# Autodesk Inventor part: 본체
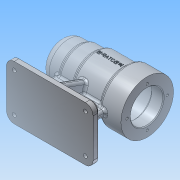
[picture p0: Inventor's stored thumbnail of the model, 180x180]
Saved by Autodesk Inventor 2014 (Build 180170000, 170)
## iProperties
Created: 2016-06
Part Number: 본체
Material: 알루미늄 6061
Document SubType Name: Modeling
Designer: net
Density: 2.71 g/cm^3
Appearance: 알루미늄 - 평지
Author: net
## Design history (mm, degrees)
sketch "스케치2"
  geometry: L1 (46, 35)-(-46, 35); L2 (-56, 25)-(-56, -25); L3 (-46, -35)-(46, -35); L4 (56, -25)-(56, 25); A1 r 10 centre (46, -25) between (46, -35) and (56, -25); A2 r 10 centre (46, 25) between (56, 25) and (46, 35); A3 r 10 centre (-46, 25) between (-46, 35) and (-56, 25); A4 r 10 centre (-46, -25) between (-56, -25) and (-46, -35); 1 further point
  constraints: 8 end point, 8 point on circle, 8 tangent, 4 centre point, 3 equal radius, 2 parallel, 1 horizontal, 1 perpendicular
  dimensions: "d5" = 10 radius of A1
extrude "돌출1" new body sketch "스케치2" distance "d6" = 10; taper "d7" = 0 deg
sketch "스케치3"
  geometry: A1 r 10 centre (-46, 25) between (-46, 35) and (-56, 25) reference; A2 r 10 centre (-46, -25) between (-56, -25) and (-46, -35) reference; A3 r 10 centre (46, -25) between (46, -35) and (56, -25) reference; A4 r 10 centre (46, 25) between (56, 25) and (46, 35) reference; 5 further points
  constraints: 4 coincident
hole "구멍1" sketch "스케치3" at (46, -25), (46, 25), (-46, 25), (-46, -25) diameter "d8" = 5; stored, may be unused: countersink angle "d12" = 90 deg, drill point angle "d14" = 118 deg; dims "d9" = 6, "d10" = 9, "d11" = 4, "d13" = 8
sketch "스케치4"
  geometry: L1 (-56, -25)-(-56, 25) reference; L2 (-46, 35)-(46, 35) reference; L3 (56, 25)-(56, -25) reference; L4 (46, -35)-(-46, -35) reference; L5 (36, 4)-(36, -4); L6 (-36, -4)-(-36, 4); L7 (-4, 28)-(4, 28); L8 (4, -28)-(-4, -28); L9 (4, -28)-(4, -4); L10 (4, 4)-(4, 28); L11 (-4, -28)-(-4, -4); L12 (-4, 4)-(-4, 28); L13 (-36, -4)-(-4, -4); L14 (4, -4)-(36, -4); L15 (-36, 4)-(-4, 4); L16 (4, 4)-(36, 4); C1 r 2.5 at (46, -25) reference; C2 r 2.5 at (-46, 25) reference; C3 r 2.5 at (-46, -25) reference; C4 r 2.5 at (46, 25) reference; A1 r 10 centre (-46, -25) between (-56, -25) and (-46, -35) reference; A2 r 10 centre (-46, 25) between (-46, 35) and (-56, 25) reference; A3 r 10 centre (46, 25) between (56, 25) and (46, 35) reference; A4 r 10 centre (46, -25) between (46, -35) and (56, -25) reference; 1 further point
  constraints: 24 end point
  dimensions: "d15" = 20 distance between parallel lines of L3 L5; "d16" = 20 distance between parallel lines of L6 L1; "d17" = 7 distance between parallel lines of L2 L7; "d18" = 7 distance between parallel lines of L4 L8
extrude "돌출2" join sketch "스케치4" distance "d23" = 70; taper "d24" = 0 deg
sketch "스케치5"
  geometry: L1 (0, 0)-(0, 10) reference; L2 (0, 10)-(50, 10) reference; L3 (50, 0)-(50, 10) reference; L4 (50, 0)-(0, 0) reference; L5 (21, 70)-(29, 70) reference; C1 r 25 at (25, 70); 1 further point
  constraints: 1 centre point, 1 midpoint
  dimensions: "d27" = 50 diameter of C1
extrude "돌출3" join sketch "스케치5" distance "d28" = 112; taper "d29" = 0 deg
node "작업 평면1"
sketch "스케치6"
  geometry: C1 r 27 at (0, 0); 1 further point
  constraints: 1 centre point
  dimensions: "d31" = 54 diameter of C1
extrude "돌출4" join sketch "스케치6" distance "d32" = 20; taper "d33" = 0 deg
sketch "스케치7"
  geometry: C1 r 30 at (0, 0); A1 r 25 centre (0, 0) between (4, -24.678) and (-4, -24.678) reference; 1 further point
  constraints: 1 centre point, 1 coincident
  dimensions: "d34" = 60 diameter of C1
extrude "돌출5" join sketch "스케치7" distance "d35" = 39; taper "d36" = 0 deg
sketch "스케치8"
  geometry: C1 r 34 at (0, 0); A1 r 30 centre (0, 0) between (4, -29.732) and (-4, -29.732) reference; 1 further point
  constraints: 1 centre point, 1 coincident
  dimensions: "d37" = 68 diameter of C1
extrude "돌출6" join sketch "스케치8" distance "d38" = 28; taper "d39" = 0 deg
feature "면 기울기1" dims angle "d40" = 20 deg
sketch "스케치9"
  geometry: C1 r 34 at (0, 0) reference; C2 r 21 at (0, 0); 1 further point
  constraints: 1 centre point, 1 coincident
  dimensions: "d41" = 42 diameter of C2
extrude "돌출7" cut sketch "스케치9" distance "d42" = 15; taper "d43" = 0 deg
sketch "스케치10"
  geometry: C1 r 21 at (0, 0) reference; C2 r 24 at (0, 0); 1 further point
  constraints: 1 centre point, 1 coincident
  dimensions: "d44" = 48 diameter of C2
extrude "돌출8" cut sketch "스케치10" distance "d45" = 54; taper "d46" = 0 deg
sketch "스케치11"
  geometry: C1 r 24 at (0, 0) reference; C2 r 21 at (0, 0); 1 further point
  constraints: 1 centre point, 1 coincident
  dimensions: "d47" = 42 diameter of C2
extrude "돌출9" cut sketch "스케치11" distance "d48" = 12; taper "d49" = 0 deg
sketch "스케치12"
  geometry: C1 r 21 at (0, 0) reference; C2 r 17.5 at (0, 0); 1 further point
  constraints: 1 centre point, 1 coincident
  dimensions: "d50" = 35 diameter of C2
extrude "돌출10" cut sketch "스케치12" distance "d51" = 18; taper "d52" = 0 deg
chamfer "모따기1" distance "d53" = 4; stored, may be unused: second distance "d54" = 2, angle "d55" = 45 deg
chamfer "모따기2" distance "d56" = 1; stored, may be unused: second distance "d57" = 2, angle "d58" = 45 deg
fillet "모깎기1" dims "d59" = 10
sketch "스케치13"
  geometry: C1 r 17.5 at (0, 0) reference; C2 r 10.5 at (0, 0); 1 further point
  constraints: 1 centre point, 1 coincident
  dimensions: "d60" = 21 diameter of C2
extrude "돌출11" cut sketch "스케치13" distance "d61" = 3; taper "d62" = 0 deg
fillet "모깎기2" dims "d63" = 3
fillet "모깎기3" dims "d64" = 3
fillet "모깎기4" dims "d65" = 3
fillet "모깎기5" dims "d66" = 3
fillet "모깎기6" dims "d67" = 3
fillet "모깎기7" dims "d68" = 3
fillet "모깎기8" dims "d69" = 3
node "작업 평면2"
sketch "스케치14"
  geometry: L1 (56, 36)-(56, 104) reference; L2 (56, 36)-(56, 70); 2 further points
  constraints: 2 end point, 1 midpoint, 1 other
  dimensions: "d71" = 48 distance from line of point (8, 70) L1; "d72" = 0 vertical distance of point (8, 70) L2.end
feature "엠보싱1" sketch "스케치14" dims "d73" = 0.5, "d74" = 0
sketch "스케치15"
  geometry: C1 r 34 at (0, 0) reference; C2 r 22 at (0, 0) reference; 6 further points
  constraints: 1 coincident, 6 other
  dimensions: "d75" = 26 distance of point (26, 0) C1.centre; "d78" = 360 deg dimension on point (0, 0) point (26, 0) (derived)
hole "구멍2" sketch "스케치15" at (0, 26), (26, 0), (0, -26), (-26, 0) diameter "d80" = 3.242; stored, may be unused: countersink angle "d84" = 90 deg, drill point angle "d86" = 118 deg; dims "d81" = 8, "d82" = 4, "d83" = 2, "d85" = 11
node "솔리드1"
node "절단 모서리 투영1"
node "절단 모서리 투영2"
other parameters: "d30" = -25
